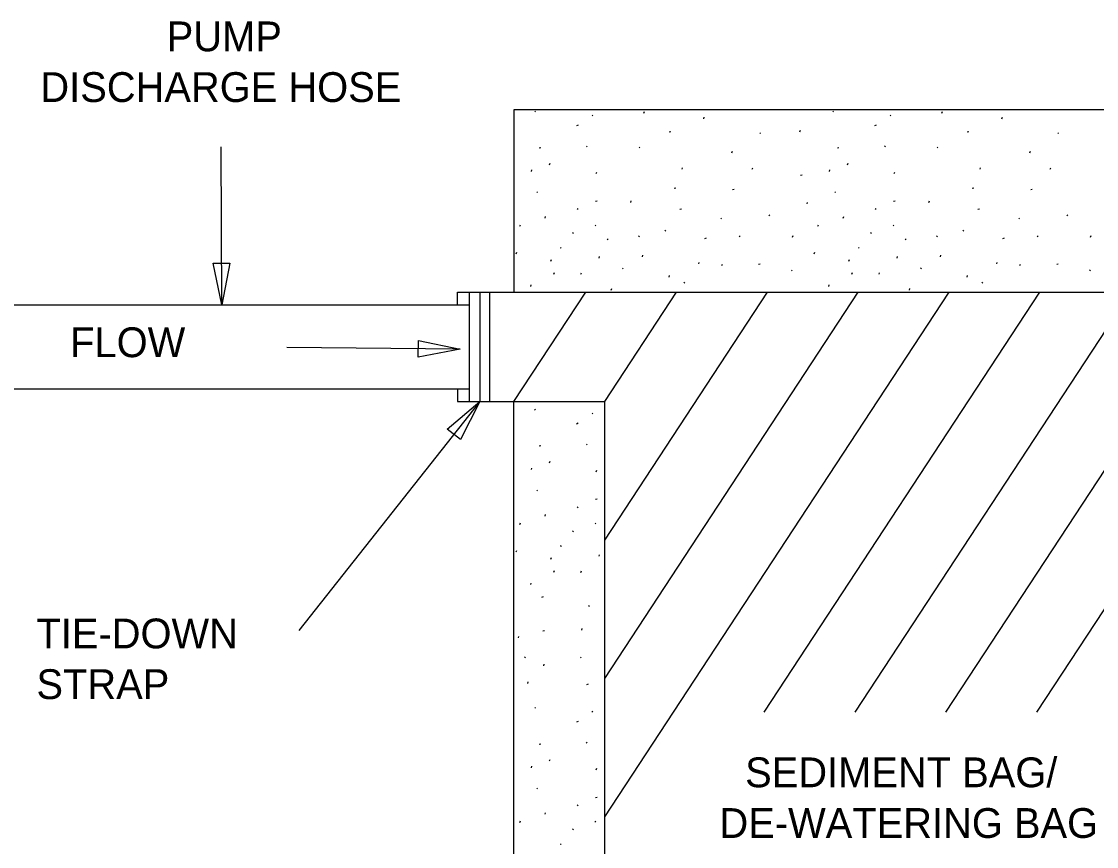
# Model space of a CAD drawing. Extents: x 0 to 34, y 0 to 22.
# Drawn here: x 4.666 to 8.047, y 8.341 to 10.936 of the extents above; entities that cross this region are included whole.
import ezdxf

# ---------------------------------------------------------------- set-up
doc = ezdxf.new("R2010")
doc.units = 0
doc.layers.add('PF_P_Text', color=7, linetype='Continuous')
doc.layers.add('SH_Text', color=7, linetype='Continuous')

msp = doc.modelspace()

# ---------------------------------------------------------------- linework, layer by layer
at = {"layer": 'SH_Text'}
for p, q in [((6.2825, 10.6511), (6.2801, 10.6536)), ((6.6234, 10.6476), (6.625, 10.6524)), ((7.22, 10.6511), (7.2176, 10.6536)), ((7.5609, 10.6476), (7.5625, 10.6524)), ((6.4628, 10.6388), (6.4604, 10.6413)), ((6.812, 10.6294), (6.8136, 10.6343)), ((7.4003, 10.6388), (7.3979, 10.6413)), ((7.7494, 10.6294), (7.7511, 10.6343)), ((6.4164, 10.6096), (6.4115, 10.6072)), ((6.7079, 10.5883), (6.7029, 10.5872)), ((6.9906, 10.5831), (6.9881, 10.5856)), ((7.1141, 10.5886), (7.1157, 10.5935)), ((7.3539, 10.6096), (7.349, 10.6072)), ((7.6454, 10.5883), (7.6404, 10.5872)), ((7.9281, 10.5831), (7.9256, 10.5856)), ((5.2955, 10.0441), (5.2939, 10.5418)), ((6.2997, 10.5384), (6.2947, 10.5373)), ((6.4457, 10.5414), (6.4433, 10.5439)), ((6.6112, 10.5378), (6.6087, 10.5402)), ((6.9006, 10.5229), (6.9022, 10.5278)), ((7.2372, 10.5384), (7.2322, 10.5373)), ((7.3832, 10.5414), (7.3808, 10.5439)), ((7.5487, 10.5378), (7.5462, 10.5402)), ((7.8381, 10.5229), (7.8397, 10.5278)), ((6.3266, 10.4851), (6.3283, 10.49)), ((7.2641, 10.4851), (7.2658, 10.49)), ((6.2698, 10.4639), (6.2714, 10.4688)), ((6.4734, 10.4571), (6.4751, 10.462)), ((6.7438, 10.4707), (6.7454, 10.4756)), ((6.9642, 10.4707), (6.9658, 10.4756)), ((7.1214, 10.4523), (7.1164, 10.4512)), ((7.2073, 10.4639), (7.2089, 10.4688)), ((7.4109, 10.4571), (7.4126, 10.462)), ((7.6813, 10.4707), (7.6829, 10.4756)), ((7.9017, 10.4707), (7.9033, 10.4756)), ((6.2893, 10.3973), (6.2869, 10.3997)), ((6.7238, 10.4115), (6.7188, 10.4104)), ((6.9078, 10.4069), (6.9028, 10.4058)), ((7.2268, 10.3973), (7.2244, 10.3997)), ((7.6613, 10.4115), (7.6563, 10.4104)), ((7.8453, 10.4069), (7.8403, 10.4058)), ((6.4762, 10.3707), (6.4711, 10.3696)), ((6.5825, 10.3665), (6.5841, 10.3714)), ((7.1368, 10.3619), (7.1385, 10.3668)), ((7.4137, 10.3707), (7.4086, 10.3696)), ((7.52, 10.3665), (7.5216, 10.3714)), ((6.313, 10.3174), (6.3146, 10.3222)), ((6.4164, 10.3441), (6.414, 10.3466)), ((6.742, 10.3457), (6.7369, 10.3446)), ((6.868, 10.3149), (6.8656, 10.3173)), ((7.0201, 10.3247), (7.0177, 10.3272)), ((7.2505, 10.3174), (7.2521, 10.3222)), ((7.3539, 10.3441), (7.3515, 10.3466)), ((7.6795, 10.3457), (7.6744, 10.3446)), ((7.8055, 10.3149), (7.8031, 10.3173)), ((7.9576, 10.3247), (7.9552, 10.3272)), ((6.2334, 10.2917), (6.235, 10.2965)), ((6.4726, 10.293), (6.4701, 10.2954)), ((7.1709, 10.2917), (7.1725, 10.2965)), ((7.4101, 10.293), (7.4076, 10.2954)), ((6.4018, 10.2686), (6.3993, 10.2711)), ((6.5116, 10.2491), (6.5092, 10.2516)), ((6.6093, 10.2589), (6.6068, 10.2613)), ((6.6923, 10.2759), (6.6898, 10.2784)), ((6.8192, 10.254), (6.8143, 10.2516)), ((6.9266, 10.2589), (6.9242, 10.2613)), ((7.0914, 10.2577), (7.093, 10.2626)), ((7.3393, 10.2686), (7.3368, 10.2711)), ((7.4491, 10.2491), (7.4467, 10.2516)), ((7.5468, 10.2589), (7.5443, 10.2613)), ((7.6298, 10.2759), (7.6273, 10.2784)), ((7.7567, 10.254), (7.7518, 10.2516)), ((7.8641, 10.2589), (7.8617, 10.2613)), ((8.0289, 10.2577), (8.0305, 10.2626)), ((6.3607, 10.2247), (6.3627, 10.2236)), ((6.3627, 10.2236), (6.3637, 10.2225)), ((7.2982, 10.2247), (7.3002, 10.2236)), ((7.3002, 10.2236), (7.3012, 10.2225)), ((6.2221, 10.2049), (6.2238, 10.2098)), ((6.3312, 10.1823), (6.3328, 10.1872)), ((6.4826, 10.1913), (6.4842, 10.1962)), ((6.6189, 10.1959), (6.6206, 10.2008)), ((6.7961, 10.1732), (6.7978, 10.1781)), ((7.1596, 10.2049), (7.1613, 10.2098)), ((7.2687, 10.1823), (7.2703, 10.1872)), ((7.4201, 10.1913), (7.4217, 10.1962)), ((7.5564, 10.1959), (7.5581, 10.2008)), ((7.7336, 10.1732), (7.7353, 10.1781)), ((6.3403, 10.1415), (6.3419, 10.1464)), ((6.4257, 10.1407), (6.4274, 10.1456)), ((6.5589, 10.1579), (6.5565, 10.1603)), ((6.8687, 10.1679), (6.8704, 10.1728)), ((6.9896, 10.1721), (6.9846, 10.171)), ((7.0905, 10.1511), (7.0881, 10.1535)), ((7.2778, 10.1415), (7.2794, 10.1464)), ((7.3632, 10.1407), (7.3649, 10.1456)), ((7.4964, 10.1579), (7.494, 10.1603)), ((7.8062, 10.1679), (7.8079, 10.1728)), ((7.9271, 10.1721), (7.9221, 10.171)), ((8.028, 10.1511), (8.0256, 10.1535)), ((6.7029, 10.1317), (6.7045, 10.1365)), ((6.752, 10.1126), (6.7496, 10.115)), ((7.6404, 10.1317), (7.642, 10.1365)), ((7.6895, 10.1126), (7.6871, 10.115)), ((6.0755, 9.7403), (6.0755, 10.0856)), ((6.1071, 10.0844), (6.1071, 9.7403)), ((6.1384, 10.0844), (6.1384, 9.7403)), ((6.215, 9.7403), (6.4408, 10.0844)), ((6.2675, 10.1022), (6.2691, 10.1071)), ((6.5007, 9.7403), (6.7265, 10.0844)), ((6.5007, 9.3049), (7.0122, 10.0844)), ((6.5007, 8.8695), (7.2979, 10.0844)), ((6.5211, 10.0909), (6.5228, 10.0957)), ((6.7167, 8.7633), (7.5836, 10.0844)), ((7.0024, 8.7633), (7.8693, 10.0844)), ((7.205, 10.1022), (7.2066, 10.1071)), ((7.2881, 8.7633), (8.155, 10.0844)), ((7.4586, 10.0909), (7.4603, 10.0957)), ((7.5738, 8.7633), (8.4407, 10.0844)), ((4.616, 10.0441), (6.0755, 10.0441)), ((6.0453, 9.9051), (5.5009, 9.91)), ((4.616, 9.7805), (6.0755, 9.7805)), ((6.1071, 9.7403), (5.5386, 9.0206)), ((6.1384, 9.7403), (6.5007, 9.7403)), ((6.2825, 9.7136), (6.2801, 9.7161)), ((7.8595, 8.7633), (8.4817, 9.7115)), ((6.4164, 9.6721), (6.4115, 9.6697)), ((6.4628, 9.7014), (6.4604, 9.7038)), ((6.4457, 9.6039), (6.4433, 9.6064)), ((6.2997, 9.6009), (6.2947, 9.5998)), ((6.3266, 9.5476), (6.3283, 9.5525)), ((6.2698, 9.5264), (6.2714, 9.5313)), ((6.4734, 9.5197), (6.4751, 9.5245)), ((6.2893, 9.4598), (6.2869, 9.4622)), ((6.4164, 9.4066), (6.414, 9.4091)), ((6.4762, 9.4332), (6.4711, 9.4321)), ((6.313, 9.3799), (6.3146, 9.3847)), ((6.2334, 9.3542), (6.235, 9.3591)), ((6.4018, 9.3311), (6.3993, 9.3336)), ((6.4726, 9.3555), (6.4701, 9.3579)), ((6.2221, 9.2674), (6.2238, 9.2723)), ((6.3607, 9.2872), (6.3627, 9.2862)), ((6.3627, 9.2862), (6.3637, 9.285)), ((6.3312, 9.2448), (6.3328, 9.2497)), ((6.4826, 9.2539), (6.4842, 9.2587)), ((6.3403, 9.204), (6.3419, 9.2089)), ((6.4257, 9.2032), (6.4274, 9.2081)), ((6.2675, 9.1647), (6.2691, 9.1696)), ((6.3066, 9.1258), (6.3015, 9.1247)), ((6.4521, 9.0957), (6.4497, 9.0982)), ((6.2289, 8.997), (6.2305, 9.0018)), ((6.3111, 9.0193), (6.3061, 9.0182)), ((6.428, 9.0219), (6.4296, 9.0268)), ((6.2507, 8.9348), (6.2483, 8.9372)), ((6.4262, 8.9343), (6.4237, 8.9368)), ((6.3085, 8.9093), (6.3101, 8.9142)), ((6.2584, 8.8542), (6.26, 8.859)), ((6.4482, 8.8515), (6.4433, 8.8491)), ((6.2825, 8.7761), (6.2801, 8.7786)), ((6.4628, 8.7639), (6.4604, 8.7663)), ((6.5007, 8.4341), (6.7167, 8.7633)), ((6.4164, 8.7346), (6.4115, 8.7322)), ((6.2997, 8.6634), (6.2947, 8.6623)), ((6.4457, 8.6664), (6.4433, 8.6689)), ((6.2698, 8.5889), (6.2714, 8.5938)), ((6.3266, 8.6101), (6.3283, 8.615)), ((6.4734, 8.5822), (6.4751, 8.587)), ((6.2893, 8.5223), (6.2869, 8.5247)), ((6.4762, 8.4957), (6.4711, 8.4946)), ((6.4164, 8.4691), (6.414, 8.4716)), ((6.2334, 8.4167), (6.235, 8.4216)), ((6.313, 8.4424), (6.3146, 8.4472)), ((6.4726, 8.418), (6.4701, 8.4204)), ((6.4018, 8.3936), (6.3993, 8.3961)), ((6.3607, 8.3497), (6.3627, 8.3487)), ((6.3627, 8.3487), (6.3637, 8.3475))]:
    msp.add_line(p, q, dxfattribs=at)
for points in [[(10.0688, 9.8619), (10.0688, 10.6578), (6.215, 10.6578), (6.215, 10.0844)], [(6.0374, 10.0441), (6.0374, 10.0844), (6.1384, 10.0844)], [(6.1384, 10.0844), (8.4817, 10.0844), (8.4817, 6.8139), (6.5007, 6.8139), (6.5007, 9.7403)], [(6.215, 10.0844), (6.4408, 10.0844), (6.7265, 10.0844), (7.0122, 10.0844), (7.2979, 10.0844), (7.5836, 10.0844), (7.8693, 10.0844), (8.155, 10.0844), (8.4407, 10.0844), (8.4817, 10.0844), (8.4817, 9.8619)], [(10.0688, 9.8619), (10.0688, 5.4707), (6.215, 5.4707), (6.215, 9.7403)], [(6.0374, 9.7805), (6.0374, 9.7403), (6.1384, 9.7403)]]:
    msp.add_lwpolyline(points, dxfattribs=at)
for points in [[(5.3214, 10.1755), (5.2955, 10.0441), (5.2689, 10.1753)], [(5.9143, 9.9325), (6.0453, 9.9051), (5.9138, 9.88)], [(6.0052, 9.6536), (6.1071, 9.7403), (6.0464, 9.621)]]:
    msp.add_lwpolyline(points, close=True, dxfattribs=at)

# ---------------------------------------------------------------- texts
at = {"layer": 'PF_P_Text'}
for s, p in [('PUMP', (5.1227, 10.8418)), ('DISCHARGE HOSE', (4.7252, 10.6824)), ('FLOW', (4.8189, 9.88)), ('TIE-DOWN', (4.7129, 8.9642)), ('STRAP', (4.7129, 8.8048)), ('SEDIMENT BAG/', (6.9421, 8.5275)), ('DE-WATERING BAG', (6.8613, 8.3681))]:
    msp.add_text(s, height=0.09375, dxfattribs=at).set_placement(p)

doc.saveas('drawing.dxf')
